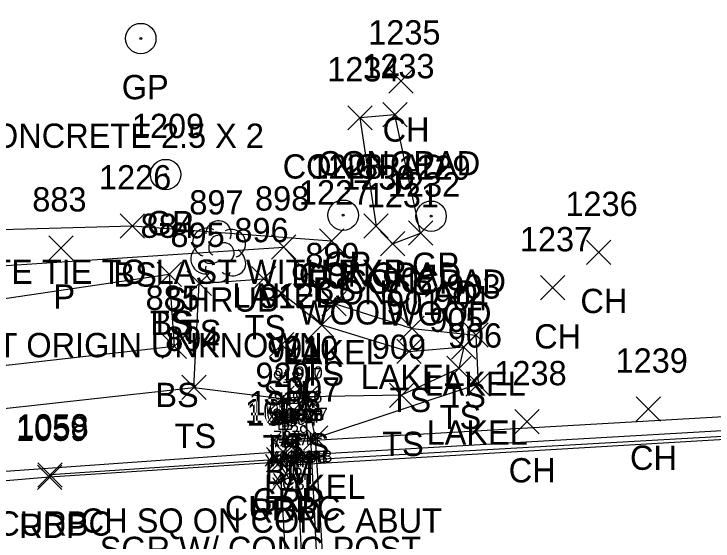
# Model space of a CAD drawing. Extents: x 1715662 to 1717487, y 887396 to 890004.
# Drawn here: x 1716855 to 1716912.5, y 888236.3 to 888279.7 of the extents above; entities that cross this region are included whole.
import ezdxf

# ---------------------------------------------------------------- set-up
doc = ezdxf.new("R2010")
doc.units = 0
for name, color, linetype in [('B_A', 7, 'Continuous'), ('B_I', 7, 'Continuous'), ('B_TIC', 7, 'Continuous'), ('BDC', 7, 'Continuous'), ('BF', 7, 'Continuous'), ('BR', 7, 'Continuous'), ('BSE', 7, 'Continuous'), ('BSUBM', 7, 'Continuous'), ('C_A', 7, 'Continuous'), ('C_C', 7, 'Continuous'), ('C_I', 7, 'Continuous'), ('CPBM', 7, 'Continuous'), ('D_A', 7, 'Continuous'), ('D_C', 7, 'Continuous'), ('D_I', 7, 'Continuous'), ('D_TIC', 7, 'Continuous'), ('L_A', 7, 'Continuous'), ('L_I', 7, 'Continuous'), ('L_TIC', 7, 'Continuous'), ('LAWE', 7, 'Continuous'), ('LELB', 7, 'Continuous'), ('LS', 7, 'Continuous'), ('LSH', 7, 'Continuous'), ('P_A', 7, 'Continuous'), ('P_I', 7, 'Continuous'), ('P_TIC', 7, 'Continuous'), ('PET', 7, 'Continuous'), ('R_A', 7, 'Continuous'), ('R_C', 7, 'Continuous'), ('R_I', 7, 'Continuous'), ('R_TIC', 7, 'Continuous'), ('RC', 7, 'Continuous'), ('RGP', 7, 'Continuous'), ('RGR', 7, 'Continuous')]:
    doc.layers.add(name, color=color, linetype=linetype)

msp = doc.modelspace()

# ---------------------------------------------------------------- linework, layer by layer
at = {"layer": 'B_TIC'}
for p, q in [((1716879.094, 888248.225), (1716879.169, 888248.225)), ((1716877.033, 888248.088), (1716877.108, 888248.088)), ((1716877.197, 888247.861), (1716877.272, 888247.861)), ((1716878.974, 888248.087), (1716879.049, 888248.087)), ((1716877.278, 888246.136), (1716877.354, 888246.136)), ((1716879.046, 888246.236), (1716879.121, 888246.236)), ((1716877.138, 888244.751), (1716877.214, 888244.751)), ((1716877.276, 888244.688), (1716877.351, 888244.688)), ((1716878.173, 888244.72), (1716878.249, 888244.72)), ((1716879.151, 888244.793), (1716879.226, 888244.793)), ((1716879.373, 888244.78), (1716879.449, 888244.78)), ((1716879.797, 888244.823), (1716879.873, 888244.823)), ((1716877.305, 888244.49), (1716877.38, 888244.49)), ((1716877.305, 888244.49), (1716877.38, 888244.49)), ((1716877.965, 888244.411), (1716878.041, 888244.411)), ((1716878.145, 888243.386), (1716878.22, 888243.386)), ((1716877.426, 888242.56), (1716877.502, 888242.56)), ((1716877.5, 888242.928), (1716877.575, 888242.928))]:
    msp.add_line(p, q, dxfattribs=at)
for points in [[(1716879.09, 888247.725), (1716879.09, 888248.725)], [(1716877.029, 888247.588), (1716877.029, 888248.588)], [(1716877.193, 888247.361), (1716877.193, 888248.361)], [(1716878.59, 888248.225), (1716879.59, 888248.225)], [(1716878.97, 888247.587), (1716878.97, 888248.587)], [(1716876.529, 888248.088), (1716877.529, 888248.088)], [(1716876.693, 888247.861), (1716877.693, 888247.861)], [(1716878.47, 888248.087), (1716879.47, 888248.087)], [(1716877.275, 888245.636), (1716877.275, 888246.636)], [(1716879.042, 888245.736), (1716879.042, 888246.736)], [(1716876.775, 888246.136), (1716877.775, 888246.136)], [(1716878.542, 888246.236), (1716879.542, 888246.236)], [(1716877.135, 888244.251), (1716877.135, 888245.251)], [(1716879.147, 888244.292), (1716879.147, 888245.293)], [(1716879.37, 888244.28), (1716879.37, 888245.28)], [(1716879.794, 888244.323), (1716879.794, 888245.323)], [(1716876.635, 888244.751), (1716877.635, 888244.751)], [(1716876.772, 888244.688), (1716877.772, 888244.688)], [(1716877.272, 888244.188), (1716877.272, 888245.188)], [(1716877.301, 888243.99), (1716877.301, 888244.99)], [(1716877.301, 888243.99), (1716877.301, 888244.99)], [(1716877.67, 888244.72), (1716878.67, 888244.72)], [(1716877.962, 888243.911), (1716877.962, 888244.911)], [(1716878.17, 888244.22), (1716878.17, 888245.22)], [(1716878.647, 888244.793), (1716879.647, 888244.793)], [(1716878.87, 888244.78), (1716879.87, 888244.78)], [(1716879.294, 888244.823), (1716880.294, 888244.823)], [(1716876.801, 888244.49), (1716877.801, 888244.49)], [(1716876.801, 888244.49), (1716877.801, 888244.49)], [(1716877.462, 888244.411), (1716878.462, 888244.411)], [(1716878.141, 888242.886), (1716878.141, 888243.886)], [(1716877.423, 888242.06), (1716877.423, 888243.06)], [(1716877.496, 888242.428), (1716877.496, 888243.428)], [(1716877.641, 888243.386), (1716878.641, 888243.386)], [(1716876.923, 888242.56), (1716877.923, 888242.56)], [(1716876.996, 888242.928), (1716877.996, 888242.928)]]:
    msp.add_lwpolyline(points, dxfattribs=at)
at = {"layer": 'BDC'}
for points in [[(1717176.589, 888262.234), (1717176.877, 888260.812), (1717116.829, 888257.088), (1717056.7, 888253.344), (1716997.03, 888249.858), (1716936.998, 888246.313), (1716877.496, 888242.928), (1716877.301, 888244.49)], [(1717176.976, 888262.024), (1717176.866, 888260.514), (1717116.827, 888256.946), (1717056.83, 888253.148), (1716997.002, 888249.663), (1716937.062, 888246.095), (1716877.423, 888242.56)]]:
    msp.add_lwpolyline(points, dxfattribs=at)
at = {"layer": 'BF'}
msp.add_lwpolyline([(1717176.589, 888262.234), (1717116.538, 888258.636), (1717056.61, 888254.944), (1716996.925, 888251.433), (1716937.102, 888247.945), (1716877.301, 888244.49)], dxfattribs=at)
at = {"layer": 'BR'}
msp.add_lwpolyline([(1717175.997, 888261.982), (1717175.88, 888261.141), (1717117.062, 888257.612), (1717056.557, 888253.997), (1716997.021, 888250.409), (1716936.966, 888246.784), (1716878.141, 888243.386), (1716877.962, 888244.411)], dxfattribs=at)
at = {"layer": 'BSE'}
for points in [[(1716879.79, 888212.64), (1716878.17, 888244.72)], [(1716879.37, 888244.78), (1716880.99, 888212.7)]]:
    msp.add_lwpolyline(points, dxfattribs=at)
at = {"layer": 'BSUBM'}
for points in [[(1716879.794, 888244.823), (1716879.09, 888248.225), (1716877.029, 888248.088), (1716877.135, 888244.751)], [(1716877.272, 888244.688), (1716879.147, 888244.793), (1716879.042, 888246.236), (1716878.97, 888248.087), (1716877.193, 888247.861), (1716877.275, 888246.136)], [(1716877.275, 888246.136), (1716877.272, 888244.688)], [(1716881.978, 888209.102), (1716879.794, 888244.823)]]:
    msp.add_lwpolyline(points, dxfattribs=at)
at = {"layer": 'CPBM'}
for p, q in [((1716876.798, 888245.534), (1716876.798, 888246.534)), ((1716876.798, 888246.534), (1716877.798, 888246.534)), ((1716877.798, 888246.534), (1716877.798, 888245.534)), ((1716877.3, 888246.035), (1716877.3, 888246.035)), ((1716877.3, 888246.035), (1716877.3, 888246.035)), ((1716877.798, 888245.534), (1716876.798, 888245.534))]:
    msp.add_line(p, q, dxfattribs=at)
at = {"layer": 'D_TIC'}
for points in [[(1716857.85, 888259.48), (1716859.85, 888261.48)], [(1716859.85, 888259.48), (1716857.85, 888261.48)]]:
    msp.add_lwpolyline(points, dxfattribs=at)
at = {"layer": 'L_TIC'}
for points in [[(1716885.819, 888273.226), (1716887.819, 888275.226)], [(1716887.819, 888273.226), (1716885.819, 888275.226)], [(1716885.327, 888270.447), (1716887.327, 888272.447)], [(1716887.327, 888270.447), (1716885.327, 888272.447)], [(1716882.446, 888270.19), (1716884.446, 888272.19)], [(1716884.446, 888270.19), (1716882.446, 888272.19)], [(1716863.723, 888261.295), (1716865.723, 888263.295)], [(1716865.723, 888261.295), (1716863.723, 888263.295)], [(1716883.769, 888261.285), (1716885.769, 888263.285)], [(1716885.769, 888261.285), (1716883.769, 888263.285)], [(1716887.438, 888260.705), (1716889.438, 888262.705)], [(1716889.438, 888260.705), (1716887.438, 888262.705)], [(1716880.119, 888260.054), (1716882.119, 888262.054)], [(1716882.119, 888260.054), (1716880.119, 888262.054)], [(1716876.174, 888259.555), (1716878.174, 888261.555)], [(1716878.174, 888259.555), (1716876.174, 888261.555)], [(1716885.128, 888259.824), (1716887.128, 888261.824)], [(1716887.128, 888259.824), (1716885.128, 888261.824)], [(1716902.097, 888259.113), (1716904.097, 888261.113)], [(1716904.097, 888259.113), (1716902.097, 888261.113)], [(1716866.758, 888257.309), (1716868.758, 888259.309)], [(1716868.758, 888257.309), (1716866.758, 888259.309)], [(1716866.758, 888257.309), (1716868.758, 888259.309)], [(1716868.758, 888257.309), (1716866.758, 888259.309)], [(1716869.22, 888256.561), (1716871.22, 888258.561)], [(1716871.22, 888256.561), (1716869.22, 888258.561)], [(1716874.534, 888256.948), (1716876.534, 888258.948)], [(1716876.534, 888256.948), (1716874.534, 888258.948)], [(1716898.296, 888256.2), (1716900.296, 888258.2)], [(1716900.296, 888256.2), (1716898.296, 888258.2)], [(1716880.322, 888254.897), (1716882.322, 888256.897)], [(1716882.322, 888254.897), (1716880.322, 888256.897)], [(1716879.311, 888253.139), (1716881.311, 888255.139)], [(1716881.311, 888253.139), (1716879.311, 888255.139)], [(1716886.736, 888252.856), (1716888.736, 888254.856)], [(1716888.736, 888252.856), (1716886.736, 888254.856)], [(1716891.995, 888252.305), (1716893.995, 888254.305)], [(1716893.995, 888252.305), (1716891.995, 888254.305)], [(1716867.17, 888251.377), (1716869.17, 888253.377)], [(1716869.17, 888251.377), (1716867.17, 888253.377)], [(1716875.994, 888251.519), (1716877.994, 888253.519)], [(1716877.994, 888251.519), (1716875.994, 888253.519)], [(1716890.986, 888251.334), (1716892.986, 888253.334)], [(1716892.986, 888251.334), (1716890.986, 888253.334)], [(1716886.482, 888250.965), (1716888.482, 888252.965)], [(1716888.482, 888250.965), (1716886.482, 888252.965)], [(1716890.594, 888249.562), (1716892.594, 888251.562)], [(1716892.594, 888249.562), (1716890.594, 888251.562)], [(1716868.789, 888248.001), (1716870.789, 888250.001)], [(1716870.789, 888248.001), (1716868.789, 888250.001)], [(1716868.789, 888248.001), (1716870.789, 888250.001)], [(1716870.789, 888248.001), (1716868.789, 888250.001)], [(1716892.169, 888248.274), (1716894.169, 888250.274)], [(1716894.169, 888248.274), (1716892.169, 888250.274)], [(1716885.869, 888247.35), (1716887.869, 888249.35)], [(1716887.869, 888247.35), (1716885.869, 888249.35)], [(1716876.029, 888247.088), (1716878.029, 888249.088)], [(1716878.029, 888247.088), (1716876.029, 888249.088)], [(1716878.09, 888247.225), (1716880.09, 888249.225)], [(1716880.09, 888247.225), (1716878.09, 888249.225)], [(1716906.178, 888246.209), (1716908.178, 888248.209)], [(1716908.178, 888246.209), (1716906.178, 888248.209)], [(1716896.198, 888245.174), (1716898.198, 888247.174)], [(1716898.198, 888245.174), (1716896.198, 888247.174)], [(1716878.794, 888243.823), (1716880.794, 888245.823)], [(1716880.794, 888243.823), (1716878.794, 888245.823)]]:
    msp.add_lwpolyline(points, dxfattribs=at)
at = {"layer": 'LAWE'}
msp.add_lwpolyline([(1716792.923, 888333.593), (1716808.09, 888324.58), (1716820.08, 888290.735), (1716820.719, 888281.539), (1716822.371, 888277.267), (1716826.189, 888277.556), (1716826.504, 888273.884), (1716836.716, 888265.482), (1716850.622, 888258.774), (1716877.174, 888260.555), (1716881.322, 888255.897), (1716887.736, 888253.856), (1716892.995, 888253.305), (1716893.169, 888249.274), (1716879.794, 888244.823)], dxfattribs=at)
at = {"layer": 'LELB'}
for points in [[(1716798.784, 888338.684), (1716807.198, 888328.202), (1716816.689, 888310.638), (1716822.622, 888293.629), (1716826.404, 888294.991), (1716827.92, 888291.14), (1716823.715, 888289.67), (1716822.512, 888293.041), (1716821.152, 888288.315), (1716833.507, 888272.565), (1716850.988, 888261.906), (1716864.723, 888262.295), (1716881.119, 888261.054)], [(1716791.288, 888331.615), (1716796.122, 888325.707), (1716805.751, 888321.457), (1716813.357, 888291.514), (1716815.908, 888278.599), (1716830.764, 888256.002), (1716850.124, 888255.716), (1716867.758, 888258.309)], [(1716831.352, 888253.697), (1716835.782, 888246.432), (1716841.647, 888245.886), (1716850.938, 888246.905), (1716869.789, 888249.001), (1716870.22, 888257.561), (1716875.534, 888257.948), (1716880.311, 888254.139), (1716887.482, 888251.965), (1716891.986, 888252.334), (1716891.594, 888250.562), (1716886.869, 888248.35), (1716879.09, 888248.225)], [(1716867.758, 888258.309), (1716868.17, 888252.377), (1716837.365, 888248.868), (1716835.782, 888246.432)], [(1716869.789, 888249.001), (1716877.029, 888248.088)]]:
    msp.add_lwpolyline(points, dxfattribs=at)
at = {"layer": 'LS'}
for points in [[(1716884.769, 888262.285), (1716886.128, 888260.824), (1716888.438, 888261.705), (1716886.327, 888271.447), (1716883.446, 888271.19)], [(1716883.446, 888271.19), (1716884.769, 888262.285)]]:
    msp.add_lwpolyline(points, dxfattribs=at)
at = {"layer": 'LSH'}
msp.add_line((1716871.768, 888260.233), (1716871.768, 888260.233), dxfattribs=at)
msp.add_line((1716871.768, 888260.233), (1716871.768, 888260.233), dxfattribs=at)
msp.add_arc((1716871.815, 888261.667), 1.047, 335.52715, 180.95627, dxfattribs=at)
for centre, major_axis, ratio, start_param, end_param in [((1716870.976, 888260.9), (1.21, -0.512), 0.895232, 1.570796, 4.712389), ((1716872.81, 888260.817), (-1.141, -0.483), 0.949671, 1.570796, 4.712389), ((1716871.56, 888260.692), (-0.208, -0.792), 0.645439, 3.141593, 6.283185), ((1716872.268, 888260.067), (-0.5, 0.667), 0.989748, 3.141593, 6.283185), ((1716870.685, 888259.525), (0.584, -1.042), 0.959034, 3.141593, 6.283185), ((1716872.768, 888259.4), (-1.09, 0.792), 0.841452, 1.570796, 4.712389), ((1716871.31, 888259.483), (-0.625, -0.083), 0.423636, 0, 3.141593), ((1716871.768, 888258.733), (0.265, 1.061), 0.942809, 1.570796, 4.712389)]:
    msp.add_ellipse(centre, major_axis=major_axis, ratio=ratio, start_param=start_param, end_param=end_param, dxfattribs=at)
at = {"layer": 'P_TIC'}
for points in [[(1716875.883, 888241.851), (1716877.883, 888243.851)], [(1716877.883, 888241.851), (1716875.883, 888243.851)], [(1716856.915, 888240.594), (1716858.915, 888242.594)], [(1716858.915, 888240.594), (1716856.915, 888242.594)]]:
    msp.add_lwpolyline(points, dxfattribs=at)
at = {"layer": 'PET'}
msp.add_lwpolyline([(1716669.133, 888208.315), (1716709.505, 888208.714), (1716740.373, 888211.068), (1716775.556, 888211.777), (1716802.021, 888213.013), (1716840.455, 888216.113), (1716878.657, 888218.974), (1716877.597, 888230.504), (1716876.883, 888242.851), (1716857.915, 888241.594), (1716836.634, 888239.831), (1716814.633, 888240.145), (1716785.061, 888241.323), (1716771.928, 888239.872), (1716746.815, 888241.658), (1716719.438, 888242.78), (1716699.752, 888242.907), (1716680.829, 888242.531), (1716671.322, 888244.592)], dxfattribs=at)
at = {"layer": 'R_TIC'}
for points in [[(1716876.112, 888242.702), (1716878.112, 888244.702)], [(1716878.112, 888242.702), (1716876.112, 888244.702)], [(1716875.747, 888242.054), (1716877.747, 888244.054)], [(1716877.747, 888242.054), (1716875.747, 888244.054)], [(1716856.951, 888240.793), (1716858.951, 888242.793)], [(1716858.951, 888240.793), (1716856.951, 888242.793)]]:
    msp.add_lwpolyline(points, dxfattribs=at)
at = {"layer": 'RC'}
msp.add_lwpolyline([(1716876.747, 888243.054), (1716857.951, 888241.793)], dxfattribs=at)
at = {"layer": 'RGP'}
for p, q in [((1716865.415, 888277.72), (1716865.415, 888277.72)), ((1716867.457, 888266.523), (1716867.457, 888266.523)), ((1716882.065, 888263.174), (1716882.065, 888263.174)), ((1716889.301, 888263.092), (1716889.301, 888263.092))]:
    msp.add_line(p, q, dxfattribs=at)
for centre, radius in [((1716865.415, 888277.72), 1.25), ((1716865.415, 888277.72), 0.0833), ((1716867.457, 888266.523), 1.25), ((1716867.457, 888266.523), 0.0833), ((1716882.065, 888263.174), 1.25), ((1716889.301, 888263.092), 1.25), ((1716882.065, 888263.174), 0.0833), ((1716889.301, 888263.092), 0.0833)]:
    msp.add_circle(centre, radius, dxfattribs=at)
at = {"layer": 'RGR'}
msp.add_lwpolyline([(1716877.112, 888243.702), (1716838.37, 888240.943)], dxfattribs=at)

# ---------------------------------------------------------------- texts
at = {"layer": 'B_A'}
for s, p in [('XAB', (1716875.75, 888246.088)), ('XAT', (1716877.675, 888246.087)), ('XAB', (1716877.811, 888246.225)), ('XAT', (1716875.898, 888245.861)), ('XAT', (1716875.979, 888244.136)), ('XAT', (1716877.747, 888244.236)), ('XAB', (1716875.855, 888242.751)), ('XAT', (1716875.977, 888242.688)), ('XBS', (1716876.91, 888242.72)), ('XAT', (1716877.852, 888242.793)), ('XBS', (1716878.11, 888242.78)), ('XAB', (1716878.514, 888242.823)), ('XFAT', (1716875.557, 888242.49)), ('XCT', (1716876.022, 888242.49)), ('XRF', (1716876.722, 888242.411)), ('XRF', (1716876.901, 888241.386)), ('XCT', (1716876.217, 888240.928)), ('XCB', (1716876.159, 888240.56))]:
    msp.add_text(s, height=1, dxfattribs=at).set_placement(p)
at = {"layer": 'B_I'}
for s, p in [('911', (1716876.415, 888249.588)), ('917', (1716878.073, 888249.587)), ('910', (1716878.149, 888249.725)), ('918', (1716876.295, 888249.361)), ('916', (1716878.117, 888247.736)), ('919', (1716876.373, 888247.636)), ('728', (1716876.12, 888245.99)), ('728', (1716876.12, 888245.99)), ('913', (1716876.237, 888246.251)), ('914', (1716876.375, 888246.188)), ('1382', (1716876.824, 888246.22)), ('908', (1716878.15, 888246.28)), ('915', (1716878.249, 888246.293)), ('907', (1716878.573, 888246.323)), ('730', (1716876.737, 888245.911)), ('729', (1716876.956, 888244.886)), ('727', (1716876.315, 888244.428)), ('726', (1716876.214, 888244.06))]:
    msp.add_text(s, height=1, dxfattribs=at).set_placement(p)
at = {"layer": 'C_A'}
msp.add_text('BM', height=2, dxfattribs=at).set_placement((1716875.615, 888241.035))
at = {"layer": 'C_C'}
msp.add_text('CH SQ ON CONC ABUT', height=2, dxfattribs=at).set_placement((1716860.474, 888237.035))
at = {"layer": 'C_I'}
msp.add_text('920', height=2, dxfattribs=at).set_placement((1716874.852, 888249.035))
at = {"layer": 'D_A'}
msp.add_text('P', height=2, dxfattribs=at).set_placement((1716858.227, 888255.48))
at = {"layer": 'D_C'}
msp.add_text('8 CGMP OUTLET ORIGIN UNKNOWN', height=2, dxfattribs=at).set_placement((1716833.708, 888251.48))
at = {"layer": 'D_I'}
msp.add_text('883', height=2, dxfattribs=at).set_placement((1716856.487, 888263.48))
at = {"layer": 'L_A'}
for s, p in [('CH', (1716885.307, 888269.226)), ('CONCPAD', (1716879.973, 888266.447)), ('CONCPAD', (1716877.092, 888266.19)), ('BS', (1716863.164, 888257.295)), ('CONCPAD', (1716878.415, 888257.285)), ('CONCPAD', (1716882.083, 888256.705)), ('BS', (1716879.56, 888256.054)), ('LAKEL', (1716872.938, 888255.555)), ('CONCPAD', (1716879.774, 888255.824)), ('SHRUB', (1716867.398, 888255.233)), ('CH', (1716901.585, 888255.113)), ('TS', (1716866.168, 888253.309)), ('BS', (1716866.199, 888253.309)), ('TS', (1716868.629, 888252.561)), ('TS', (1716873.944, 888252.948)), ('CH', (1716897.784, 888252.2)), ('LAKEL', (1716877.086, 888250.897)), ('TS', (1716878.721, 888249.139)), ('LAKEL', (1716883.5, 888248.856)), ('LAKEL', (1716888.759, 888248.305)), ('BS', (1716866.611, 888247.377)), ('SH', (1716875.482, 888247.519)), ('TS', (1716890.395, 888247.334)), ('TS', (1716885.891, 888246.965)), ('TS', (1716890.004, 888245.562)), ('TS', (1716868.198, 888244.001)), ('TS', (1716868.198, 888244.001)), ('LAKEL', (1716888.932, 888244.274)), ('TS', (1716877.5, 888243.225)), ('TS', (1716885.278, 888243.35)), ('TS', (1716875.439, 888243.088)), ('CH', (1716905.666, 888242.209)), ('CH', (1716895.686, 888241.174)), ('LAKEL', (1716875.558, 888239.823))]:
    msp.add_text(s, height=2, dxfattribs=at).set_placement(p)
at = {"layer": 'L_I'}
for s, p in [('1235', (1716884.126, 888277.226)), ('1233', (1716883.634, 888274.447)), ('1234', (1716880.753, 888274.19)), ('1226', (1716861.975, 888265.295)), ('1230', (1716881.989, 888265.285)), ('1232', (1716885.745, 888264.705)), ('1227', (1716878.426, 888264.054)), ('898', (1716874.812, 888263.555)), ('1231', (1716884.002, 888263.824)), ('897', (1716869.406, 888263.233)), ('1236', (1716900.349, 888263.113)), ('884', (1716865.396, 888261.309)), ('884', (1716865.396, 888261.309)), ('895', (1716867.858, 888260.561)), ('896', (1716873.117, 888260.948)), ('1237', (1716896.603, 888260.2)), ('899', (1716878.952, 888258.897)), ('900', (1716877.783, 888257.139)), ('902', (1716885.295, 888256.856)), ('903', (1716890.554, 888256.305)), ('885', (1716865.808, 888255.377)), ('912', (1716875.199, 888255.519)), ('904', (1716889.545, 888255.334)), ('901', (1716885.608, 888254.965)), ('905', (1716889.153, 888253.562)), ('894', (1716867.427, 888252.001)), ('894', (1716867.427, 888252.001)), ('906', (1716890.673, 888252.274)), ('909', (1716884.42, 888251.35)), ('911', (1716875.801, 888251.088)), ('910', (1716877.208, 888251.225)), ('1239', (1716904.477, 888250.209)), ('1238', (1716894.505, 888249.174)), ('907', (1716877.353, 888247.823))]:
    msp.add_text(s, height=2, dxfattribs=at).set_placement(p)
at = {"layer": 'P_A'}
for p in [(1716874.371, 888237.851), (1716855.403, 888236.594)]:
    msp.add_text('RDP', height=2, dxfattribs=at).set_placement(p)
at = {"layer": 'P_I'}
for s, p in [('1054', (1716874.111, 888245.851)), ('1059', (1716855.135, 888244.594))]:
    msp.add_text(s, height=2, dxfattribs=at).set_placement(p)
at = {"layer": 'R_A'}
for s, p in [('GP', (1716863.848, 888272.72)), ('GP', (1716865.89, 888261.523)), ('GP', (1716880.498, 888258.174)), ('GP', (1716887.734, 888258.092)), ('GRR', (1716874.6, 888238.702)), ('CURBC', (1716872.33, 888238.054)), ('CURBC', (1716853.534, 888236.793))]:
    msp.add_text(s, height=2, dxfattribs=at).set_placement(p)
at = {"layer": 'R_C'}
for s, p in [('CONCRETE 2.5 X 2', (1716851.32, 888268.72)), ('CONCRETE TIE TO LAST WITH RXR', (1716841.527, 888257.523)), ('WOOD', (1716878.42, 888254.174)), ('WOOD', (1716885.656, 888254.092)), ('SGR W/ CONC POST', (1716862.033, 888234.702))]:
    msp.add_text(s, height=2, dxfattribs=at).set_placement(p)
at = {"layer": 'R_I'}
for s, p in [('1209', (1716864.677, 888269.523)), ('1228', (1716879.372, 888266.174)), ('1229', (1716886.601, 888266.092)), ('1056', (1716874.285, 888246.702)), ('1055', (1716873.976, 888246.054)), ('1058', (1716855.179, 888244.793))]:
    msp.add_text(s, height=2, dxfattribs=at).set_placement(p)

doc.saveas('drawing.dxf')
